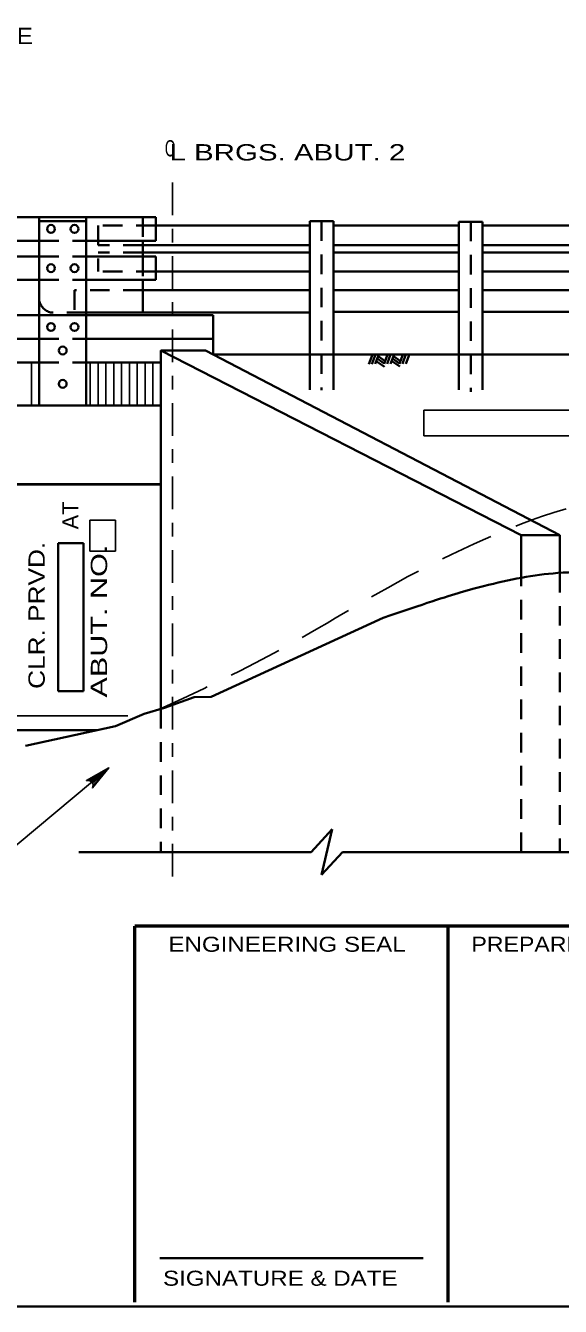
# Model space of a CAD drawing. Extents: x -11 to 79, y -154 to 0.
# Drawn here: x 11.68 to 15.61, y -65.25 to -55.84 of the extents above; entities that cross this region are included whole.
import ezdxf
from ezdxf.enums import TextEntityAlignment as Align

# ---------------------------------------------------------------- set-up
doc = ezdxf.new("R2010")
doc.units = 0
doc.header["$LTSCALE"] = 0.048
doc.linetypes.add('DOT_DASHED', pattern=[7.7, 5, -1.2, 0.3, -1.2])
doc.linetypes.add('MEDIUM_DASHED', pattern=[4.5, 3, -1.5])
for name, color, linetype, lineweight in [('1', 7, 'Continuous', 25), ('10', 7, 'Continuous', 40), ('3', 7, 'Continuous', 25), ('4', 7, 'Continuous', 25), ('5', 7, 'Continuous', 25), ('8', 7, 'Continuous', 35)]:
    doc.layers.add(name, color=color, linetype=linetype, lineweight=lineweight)

msp = doc.modelspace()

# ---------------------------------------------------------------- hatches: boundary and pattern name
at = {"layer": '4'}
msp.add_hatch(color=256, dxfattribs=at).paths.add_polyline_path([(12.18967, -61.35475), (12.21492, -61.385), (12.293, -61.29417)])

# ---------------------------------------------------------------- linework, layer by layer
at = {"layer": '1', "lineweight": 35}
msp.add_lwpolyline([(1.75, -65.25), (33.25, -65.25), (33.25, -44.75), (1.75, -44.75)], close=True, dxfattribs=at)
at = {"layer": '3', "lineweight": 35}
for p, q in [((5.56042, -57.24708), (12.63733, -57.24708)), ((11.78058, -57.24708), (11.78058, -58.63125)), ((11.78058, -57.27592), (12.12658, -57.27592)), ((12.12658, -57.24708), (12.12658, -58.63125)), ((12.63733, -57.24708), (12.63733, -57.42008)), ((13.77008, -57.27758), (13.94308, -57.27758)), ((13.77008, -58.25633), (13.77008, -57.27758)), ((13.94308, -58.25633), (13.94308, -57.27758)), ((14.86583, -57.28067), (15.03883, -57.28067)), ((14.86583, -58.25633), (14.86583, -57.28067)), ((15.03883, -58.25633), (15.03883, -57.28067)), ((12.63733, -57.30808), (13.77008, -57.30808)), ((13.94308, -57.3095), (14.86583, -57.3095)), ((15.03883, -57.3095), (15.69325, -57.3095)), ((10.22342, -57.42008), (11.78058, -57.42008)), ((12.12658, -57.42008), (12.63733, -57.42008)), ((12.54208, -57.42008), (12.54208, -57.5355)), ((12.54208, -57.45408), (13.77008, -57.45408)), ((13.94308, -57.45408), (14.86583, -57.45408)), ((15.03883, -57.45408), (15.72608, -57.45408)), ((10.22342, -57.5355), (11.78058, -57.5355)), ((12.12658, -57.5355), (12.63733, -57.5355)), ((12.54208, -57.50617), (13.77008, -57.50617)), ((12.63733, -57.5355), (12.63733, -57.7085)), ((13.94308, -57.50617), (14.86583, -57.50617)), ((15.03883, -57.50617), (15.78808, -57.50617)), ((12.63733, -57.6475), (13.77008, -57.6475)), ((13.94308, -57.6475), (14.86583, -57.6475)), ((15.03883, -57.6475), (15.79425, -57.6475)), ((10.22342, -57.7085), (11.78058, -57.7085)), ((12.12658, -57.7085), (12.63733, -57.7085)), ((12.54208, -57.7085), (12.54208, -57.947)), ((12.54208, -57.78417), (13.77008, -57.78417)), ((13.94308, -57.78417), (14.86583, -57.78417)), ((15.03883, -57.78417), (15.9705, -57.78417)), ((12.12642, -57.947), (13.77008, -57.947)), ((14.86583, -57.94242), (13.94308, -57.94242)), ((16.02033, -57.94242), (15.03883, -57.94242)), ((10.22342, -57.968), (11.78058, -57.968)), ((11.78058, -57.968), (12.12658, -57.968)), ((12.12658, -57.968), (13.05858, -57.968)), ((13.05858, -58.25633), (13.05858, -57.968)), ((10.22342, -58.141), (11.78058, -58.141)), ((12.12658, -58.141), (13.05858, -58.141)), ((12.67467, -58.2275), (15.32283, -59.58275)), ((13.00317, -58.2275), (15.60825, -59.58275)), ((10.22342, -58.314), (11.78058, -58.314)), ((12.12658, -58.314), (12.67467, -58.314)), ((13.05858, -58.25633), (16.35442, -58.25633)), ((13.77008, -58.25633), (13.77008, -58.51583)), ((13.94308, -58.25633), (13.94308, -58.51583)), ((14.22942, -58.25633), (14.20275, -58.32658)), ((14.25133, -58.256), (14.22467, -58.32625)), ((14.27683, -58.25558), (14.25017, -58.32583)), ((14.25817, -58.30442), (14.31817, -58.346)), ((14.265, -58.2865), (14.31667, -58.32225)), ((14.2715, -58.26933), (14.32308, -58.30517)), ((14.34192, -58.25558), (14.31567, -58.32483)), ((14.36383, -58.25542), (14.33758, -58.32442)), ((14.38917, -58.25517), (14.36308, -58.32408)), ((14.37058, -58.304), (14.43058, -58.34558)), ((14.37742, -58.28608), (14.429, -58.32183)), ((14.38383, -58.26892), (14.4355, -58.30475)), ((14.45433, -58.25517), (14.42808, -58.32442)), ((14.47617, -58.255), (14.45, -58.32408)), ((14.50158, -58.25483), (14.4755, -58.32367)), ((14.86583, -58.25633), (14.86583, -58.51583)), ((15.03883, -58.25633), (15.03883, -58.51583)), ((12.67467, -58.4005), (12.67467, -60.86058)), ((5.52325, -58.63125), (12.67467, -58.63125)), ((15.32283, -59.58275), (15.60825, -59.58275)), ((15.32283, -59.89667), (15.32283, -59.58275)), ((15.60825, -59.58275), (15.60825, -59.86058)), ((14.30883, -60.19208), (13.04533, -60.77158)), ((13.04533, -60.77158), (12.91933, -60.77467)), ((5.77742, -61.016), (12.20667, -61.016)), ((13.77908, -61.91158), (13.93283, -61.74475)), ((13.93283, -61.74475), (13.85583, -62.0785)), ((12.07175, -61.91158), (13.77908, -61.91158)), ((13.85583, -62.0785), (14.00958, -61.91158)), ((14.00958, -61.91158), (15.88267, -61.91158))]:
    msp.add_line(p, q, dxfattribs=at)
at = {"layer": '3', "linetype": 'MEDIUM_DASHED', "lineweight": 35}
for p, q in [((12.54208, -57.24708), (12.54208, -57.42008)), ((13.85658, -57.27758), (13.85658, -58.51892)), ((14.95233, -57.28067), (14.95233, -58.52983)), ((12.63733, -57.30808), (12.21333, -57.30808)), ((12.21333, -57.30808), (12.21333, -57.6475)), ((11.78058, -57.42008), (12.12658, -57.42008)), ((12.54208, -57.45408), (12.21333, -57.45408)), ((11.78058, -57.5355), (12.12658, -57.5355)), ((12.54208, -57.50617), (12.21333, -57.50617)), ((12.54208, -57.5355), (12.54208, -57.7085)), ((12.63733, -57.6475), (12.21333, -57.6475)), ((11.78058, -57.7085), (12.12658, -57.7085)), ((12.12675, -57.947), (11.86333, -57.947)), ((11.78058, -58.141), (12.12658, -58.141)), ((11.78058, -58.314), (12.12658, -58.314)), ((15.32283, -61.91158), (15.32283, -59.89667)), ((15.60825, -59.86058), (15.60825, -61.91158)), ((12.67467, -60.86058), (12.67467, -61.91158))]:
    msp.add_line(p, q, dxfattribs=at)
at = {"layer": '3'}
msp.add_line((5.52325, -58.63117), (12.67467, -58.63117), dxfattribs=at)
at = {"layer": '3', "lineweight": 40}
msp.add_line((5.52325, -59.20783), (12.67467, -59.20783), dxfattribs=at)
at = {"layer": '3', "linetype": 'MEDIUM_DASHED', "lineweight": 35}
msp.add_lwpolyline([(12.54208, -57.78417), (12.0395, -57.78417), (12.0395, -57.947)], dxfattribs=at)
at = {"layer": '3', "lineweight": 35}
msp.add_lwpolyline([(12.67467, -58.4005), (12.67467, -58.2275), (13.00317, -58.2275)], dxfattribs=at)
for centre in [(11.867, -57.33359), (12.04002, -57.33359), (11.867, -57.62194), (12.04002, -57.62194), (11.86699, -58.05451), (12.04, -58.05451), (11.9535, -58.22691), (11.95353, -58.472)]:
    msp.add_circle(centre, 0.02883, dxfattribs=at)
at = {"layer": '3'}
msp.add_circle((11.95353, -58.47195), 0.02883, dxfattribs=at)
at = {"layer": '3', "linetype": 'MEDIUM_DASHED', "lineweight": 35}
msp.add_arc((11.89545, -57.83358), 0.1179, 193.19618, 254.16171, dxfattribs=at)
at = {"layer": '3', "lineweight": 35}
msp.add_open_spline([(14.30883, -60.19208), (14.62, -60.08475), (14.90592, -59.99158), (15.19175, -59.92175), (15.46175, -59.86933), (15.71583, -59.85192), (16.05733, -59.84608), (16.29558, -59.82275)], degree=3, dxfattribs=at)
at = {"layer": '4', "linetype": 'DOT_DASHED'}
msp.add_line((12.76092, -56.99267), (12.76092, -62.14717), dxfattribs=at)
at = {"layer": '4'}
for p, q in [((14.60825, -58.85342), (14.60825, -58.66525)), ((12.15275, -59.4725), (12.15275, -59.70242)), ((12.34092, -59.4725), (12.15275, -59.4725)), ((12.34092, -59.70242), (12.34092, -59.4725)), ((12.34092, -59.70242), (12.15275, -59.70242)), ((11.19925, -60.91042), (12.43233, -60.91042))]:
    msp.add_line(p, q, dxfattribs=at)
at = {"layer": '4', "lineweight": 35}
for p, q in [((11.91892, -59.64283), (11.91892, -60.72875)), ((12.10717, -59.64283), (11.91892, -59.64283)), ((12.10717, -60.72875), (12.10717, -59.64283)), ((12.10717, -60.72875), (11.91892, -60.72875)), ((14.60183, -64.89675), (12.66708, -64.89675))]:
    msp.add_line(p, q, dxfattribs=at)
at = {"layer": '4', "lineweight": 53}
for p, q in [((12.48275, -65.21967), (12.48275, -62.45567)), ((18.01075, -62.45567), (12.48275, -62.45567)), ((14.78617, -65.21967), (14.78617, -62.45567))]:
    msp.add_line(p, q, dxfattribs=at)
at = {"layer": '4'}
for points in [[(14.60825, -58.85342), (15.69417, -58.85342), (15.69417, -58.66525), (14.60825, -58.66525)], [(12.293, -61.29417), (11.22725, -62.18325), (10.14683, -62.18325)], [(12.293, -61.29417), (12.17225, -61.44042), (12.17692, -61.42358), (12.17458, -61.40925), (12.16825, -61.39825), (12.15858, -61.39), (12.14483, -61.38517), (12.1275, -61.38675), (12.293, -61.29417), (12.14483, -61.38517), (12.15858, -61.39), (12.293, -61.29417), (12.16825, -61.39825), (12.17458, -61.40925), (12.293, -61.29417), (12.17692, -61.42358)]]:
    msp.add_lwpolyline(points, dxfattribs=at)
at = {"layer": '4', "lineweight": 35}
msp.add_lwpolyline([(11.68058, -61.13267), (12.34117, -60.98617), (12.55142, -60.89633), (12.70208, -60.85267), (12.91933, -60.77467)], dxfattribs=at)
at = {"layer": '4'}
msp.add_lwpolyline([(12.18967, -61.35475), (12.21492, -61.385), (12.293, -61.29417)], close=True, dxfattribs=at)
at = {"layer": '5'}
for p, q in [((11.72292, -58.314), (11.72292, -58.63117)), ((12.15558, -58.314), (12.15558, -58.63117)), ((12.21325, -58.314), (12.21325, -58.63117)), ((12.27092, -58.314), (12.27092, -58.63117)), ((12.32858, -58.314), (12.32858, -58.63117)), ((12.38625, -58.314), (12.38625, -58.63117)), ((12.44392, -58.314), (12.44392, -58.63117)), ((12.50158, -58.314), (12.50158, -58.63117)), ((12.55925, -58.314), (12.55925, -58.63117)), ((12.617, -58.314), (12.617, -58.63117))]:
    msp.add_line(p, q, dxfattribs=at)
at = {"layer": '8', "lineweight": 25}
for p, q in [((15.39625, -59.47442), (15.479, -59.44442)), ((15.479, -59.44442), (15.56375, -59.4165)), ((15.56375, -59.4165), (15.65367, -59.39067)), ((15.28325, -59.51817), (15.31325, -59.50625)), ((15.31325, -59.50625), (15.39625, -59.47442)), ((14.89342, -59.68625), (14.97708, -59.64783)), ((14.97708, -59.64783), (15.06117, -59.61058)), ((15.06117, -59.61058), (15.10133, -59.59333)), ((14.74383, -59.75808), (14.8105, -59.7255)), ((14.8105, -59.7255), (14.89342, -59.68625)), ((14.49108, -59.88842), (14.56842, -59.84733)), ((14.34225, -59.97), (14.4155, -59.92933)), ((14.4155, -59.92933), (14.49108, -59.88842)), ((14.22358, -60.03725), (14.27142, -60.00983)), ((14.27142, -60.00983), (14.34225, -59.97)), ((13.89717, -60.22917), (13.95683, -60.19383)), ((13.95683, -60.19383), (14.01608, -60.15867)), ((14.01608, -60.15867), (14.05358, -60.1365)), ((13.71392, -60.3355), (13.77217, -60.30217)), ((13.77217, -60.30217), (13.83608, -60.26508)), ((13.83608, -60.26508), (13.89717, -60.22917)), ((13.3665, -60.52467), (13.46433, -60.47325)), ((13.46433, -60.47325), (13.54192, -60.43142)), ((13.19242, -60.61258), (13.25667, -60.58075)), ((13.25667, -60.58075), (13.3665, -60.52467)), ((12.65867, -60.86517), (12.83575, -60.78375)), ((12.83575, -60.78375), (12.99325, -60.70967)), ((12.99325, -60.70967), (13.01558, -60.69892))]:
    msp.add_line(p, q, dxfattribs=at)

# ---------------------------------------------------------------- texts
at = {"layer": '10', "width": 1.2}
for s, p in [('ENGINEERING SEAL', (13.60225, -62.64458)), ('SIGNATURE & DATE', (13.55279, -65.09833))]:
    msp.add_text(s, height=0.1105, dxfattribs=at).set_placement(p, align=Align.CENTER)
at = {"layer": '10', "width": 1.15}
msp.add_text('PREPARED BY:', height=0.1105, dxfattribs=at).set_placement((14.95767, -62.64458))
at = {"layer": '4'}
for s, width, p in [('NO SCALE', 1.1, (10.84158, -55.97608)), ('C', 0.65, (12.70375, -56.80108)), ('L BRGS. ABUT. 2', 1.35, (12.73817, -56.83083))]:
    msp.add_text(s, height=0.12, dxfattribs=dict(at, width=width)).set_placement(p)
msp.add_text('AT', height=0.12, rotation=90, dxfattribs=at).set_placement((12.06933, -59.54108))
for s, width, p in [('CLR. PRVD.', 1.2, (11.82133, -60.71308)), ('ABUT. NO. ', 1.4, (12.27967, -60.777))]:
    msp.add_text(s, height=0.12, rotation=90, dxfattribs=dict(at, width=width)).set_placement(p)

doc.saveas('drawing.dxf')
